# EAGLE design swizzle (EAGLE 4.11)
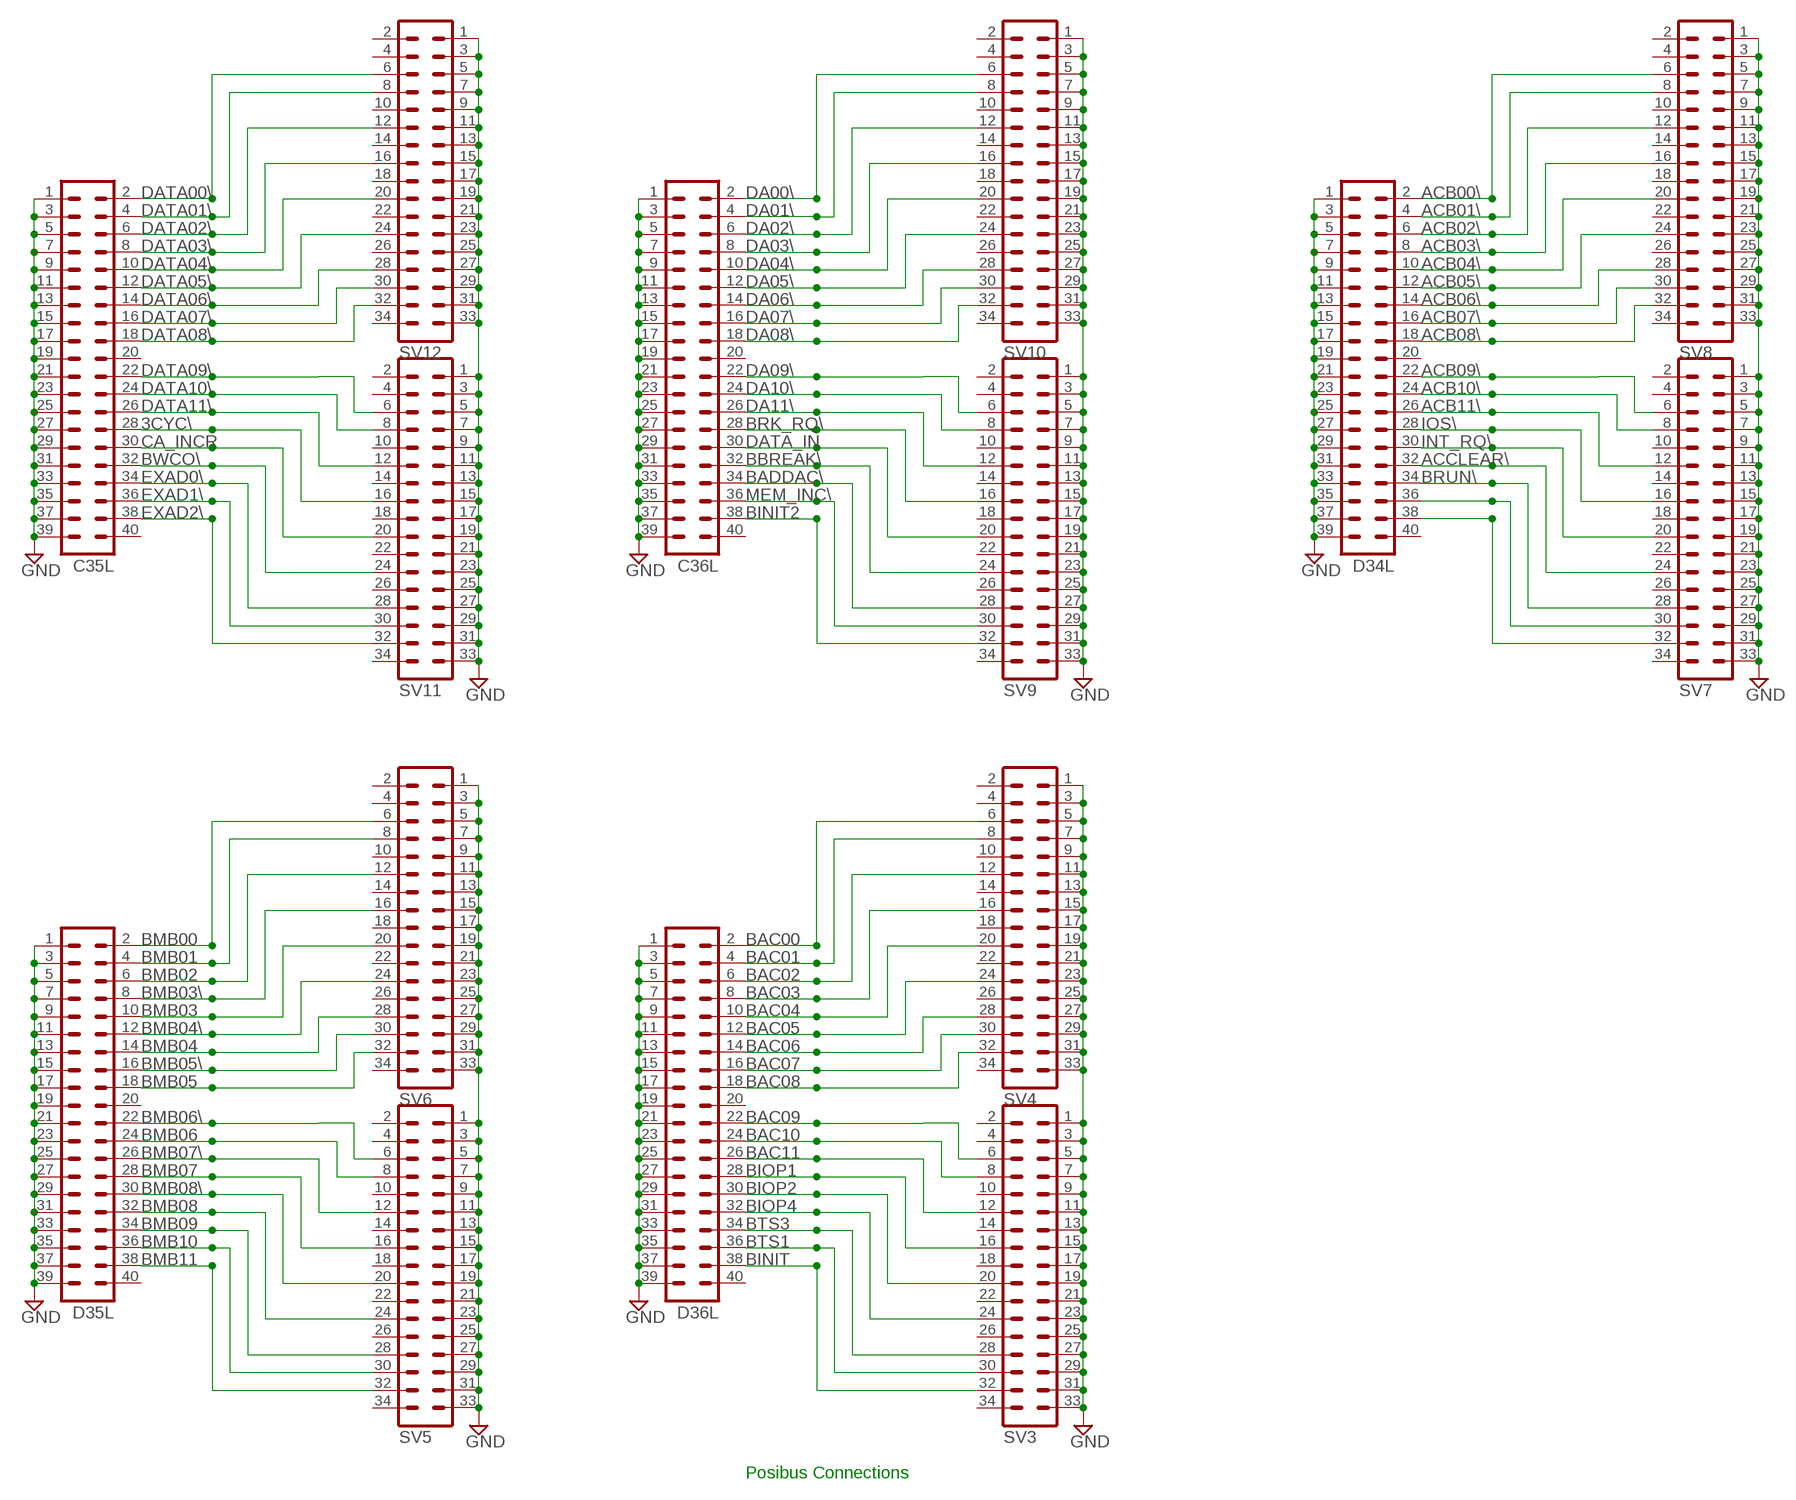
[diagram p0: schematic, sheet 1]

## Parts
C35L  MA20-2  [MA20-2]
C36L  MA20-2  [MA20-2]
D34L  MA20-2  [MA20-2]
D35L  MA20-2  [MA20-2]
D36L  MA20-2  [MA20-2]
SV3  MA17-2  [MA17-2]
SV4  MA17-2  [MA17-2]
SV5  MA17-2  [MA17-2]
SV6  MA17-2  [MA17-2]
SV7  MA17-2  [MA17-2]
SV8  MA17-2  [MA17-2]
SV9  MA17-2  [MA17-2]
SV10  MA17-2  [MA17-2]
SV11  MA17-2  [MA17-2]
SV12  MA17-2  [MA17-2]

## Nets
3CYC\: C35L.28 SV11.16
ACB00\: D34L.2 SV8.6
ACB01\: D34L.4 SV8.8
ACB02\: D34L.6 SV8.12
ACB03\: D34L.8 SV8.16
ACB04\: D34L.10 SV8.20
ACB05\: D34L.12 SV8.24
ACB06\: D34L.14 SV8.28
ACB07\: D34L.16 SV8.30
ACB08\: D34L.18 SV8.32
ACB09\: D34L.22 SV7.6
ACB10\: D34L.24 SV7.8
ACB11\: D34L.26 SV7.12
ACCLEAR\: D34L.32 SV7.24
BAC00: D36L.2 SV4.6
BAC01: D36L.4 SV4.8
BAC02: D36L.6 SV4.12
BAC03: D36L.8 SV4.16
BAC04: D36L.10 SV4.20
BAC05: D36L.12 SV4.24
BAC06: D36L.14 SV4.28
BAC07: D36L.16 SV4.30
BAC08: D36L.18 SV4.32
BAC09: D36L.22 SV3.6
BAC10: D36L.24 SV3.8
BAC11: D36L.26 SV3.12
BADDAC\: C36L.34 SV9.28
BBREAK\: C36L.32 SV9.24
BINIT: D36L.38 SV3.32
BINIT2: C36L.38 SV9.32
BIOP1: D36L.28 SV3.16
BIOP2: D36L.30 SV3.20
BIOP4: D36L.32 SV3.24
BMB00: D35L.2 SV6.6
BMB01: D35L.4 SV6.8
BMB02: D35L.6 SV6.12
BMB03: D35L.10 SV6.20
BMB03\: D35L.8 SV6.16
BMB04: D35L.14 SV6.28
BMB04\: D35L.12 SV6.24
BMB05: D35L.18 SV6.32
BMB05\: D35L.16 SV6.30
BMB06: D35L.24 SV5.8
BMB06\: D35L.22 SV5.6
BMB07: D35L.28 SV5.16
BMB07\: D35L.26 SV5.12
BMB08: D35L.32 SV5.24
BMB08\: D35L.30 SV5.20
BMB09: D35L.34 SV5.28
BMB10: D35L.36 SV5.30
BMB11: D35L.38 SV5.32
BRK_RQ\: C36L.28 SV9.16
BRUN\: D34L.34 SV7.28
BTS1: D36L.36 SV3.30
BTS3: D36L.34 SV3.28
BWCO\: C35L.32 SV11.24
CA_INCR: C35L.30 SV11.20
DA00\: C36L.2 SV10.6
DA01\: C36L.4 SV10.8
DA02\: C36L.6 SV10.12
DA03\: C36L.8 SV10.16
DA04\: C36L.10 SV10.20
DA05\: C36L.12 SV10.24
DA06\: C36L.14 SV10.28
DA07\: C36L.16 SV10.30
DA08\: C36L.18 SV10.32
DA09\: C36L.22 SV9.6
DA10\: C36L.24 SV9.8
DA11\: C36L.26 SV9.12
DATA00\: C35L.2 SV12.6
DATA01\: C35L.4 SV12.8
DATA02\: C35L.6 SV12.12
DATA03\: C35L.8 SV12.16
DATA04\: C35L.10 SV12.20
DATA05\: C35L.12 SV12.24
DATA06\: C35L.14 SV12.28
DATA07\: C35L.16 SV12.30
DATA08\: C35L.18 SV12.32
DATA09\: C35L.22 SV11.6
DATA10\: C35L.24 SV11.8
DATA11\: C35L.26 SV11.12
DATA_IN: C36L.30 SV9.20
EXAD0\: C35L.34 SV11.28
EXAD1\: C35L.36 SV11.30
EXAD2\: C35L.38 SV11.32
GND: C35L.1 C35L.3 C35L.5 C35L.7 C35L.9 C35L.11 C35L.13 C35L.15 C35L.17 C35L.19 C35L.21 C35L.23 C35L.25 C35L.27 C35L.29 C35L.31 C35L.33 C35L.35 C35L.37 C35L.39 C36L.1 C36L.3 C36L.5 C36L.7 C36L.9 C36L.11 C36L.13 C36L.15 C36L.17 C36L.19 C36L.21 C36L.23 C36L.25 C36L.27 C36L.29 C36L.31 C36L.33 C36L.35 C36L.37 C36L.39 D34L.1 D34L.3 D34L.5 D34L.7 D34L.9 D34L.11 D34L.13 D34L.15 D34L.17 D34L.19 D34L.21 D34L.23 D34L.25 D34L.27 D34L.29 D34L.31 D34L.33 D34L.35 D34L.37 D34L.39 D35L.1 D35L.3 D35L.5 D35L.7 D35L.9 D35L.11 D35L.13 D35L.15 D35L.17 D35L.19 D35L.21 D35L.23 D35L.25 D35L.27 D35L.29 D35L.31 D35L.33 D35L.35 D35L.37 D35L.39 D36L.1 D36L.3 D36L.5 D36L.7 D36L.9 D36L.11 D36L.13 D36L.15 D36L.17 D36L.19 D36L.21 D36L.23 D36L.25 D36L.27 D36L.29 D36L.31 D36L.33 D36L.35 D36L.37 D36L.39 SV3.1 SV3.3 SV3.5 SV3.7 SV3.9 SV3.11 SV3.13 SV3.15 SV3.17 SV3.19 SV3.21 SV3.23 SV3.25 SV3.27 SV3.29 SV3.31 SV3.33 SV4.1 SV4.3 SV4.5 SV4.7 SV4.9 SV4.11 SV4.13 SV4.15 SV4.17 SV4.19 SV4.21 SV4.23 SV4.25 SV4.27 SV4.29 SV4.31 SV4.33 SV5.1 SV5.3 SV5.5 SV5.7 SV5.9 SV5.11 SV5.13 SV5.15 SV5.17 SV5.19 SV5.21 SV5.23 SV5.25 SV5.27 SV5.29 SV5.31 SV5.33 SV6.1 SV6.3 SV6.5 SV6.7 SV6.9 SV6.11 SV6.13 SV6.15 SV6.17 SV6.19 SV6.21 SV6.23 SV6.25 SV6.27 SV6.29 SV6.31 SV6.33 SV7.1 SV7.3 SV7.5 SV7.7 SV7.9 SV7.11 SV7.13 SV7.15 SV7.17 SV7.19 SV7.21 SV7.23 SV7.25 SV7.27 SV7.29 SV7.31 SV7.33 SV8.1 SV8.3 SV8.5 SV8.7 SV8.9 SV8.11 SV8.13 SV8.15 SV8.17 SV8.19 SV8.21 SV8.23 SV8.25 SV8.27 SV8.29 SV8.31 SV8.33 SV9.1 SV9.3 SV9.5 SV9.7 SV9.9 SV9.11 SV9.13 SV9.15 SV9.17 SV9.19 SV9.21 SV9.23 SV9.25 SV9.27 SV9.29 SV9.31 SV9.33 SV10.1 SV10.3 SV10.5 SV10.7 SV10.9 SV10.11 SV10.13 SV10.15 SV10.17 SV10.19 SV10.21 SV10.23 SV10.25 SV10.27 SV10.29 SV10.31 SV10.33 SV11.1 SV11.3 SV11.5 SV11.7 SV11.9 SV11.11 SV11.13 SV11.15 SV11.17 SV11.19 SV11.21 SV11.23 SV11.25 SV11.27 SV11.29 SV11.31 SV11.33 SV12.1 SV12.3 SV12.5 SV12.7 SV12.9 SV12.11 SV12.13 SV12.15 SV12.17 SV12.19 SV12.21 SV12.23 SV12.25 SV12.27 SV12.29 SV12.31 SV12.33
INT_RQ\: D34L.30 SV7.20
IOS\: D34L.28 SV7.16
MEM_INC\: C36L.36 SV9.30
N$46: D34L.36 SV7.30
N$47: D34L.38 SV7.32
Unconnected: C35L.20 C35L.40 C36L.20 C36L.40 D34L.20 D34L.40 D35L.20 D35L.40 D36L.20 D36L.40 SV3.2 SV3.4 SV3.10 SV3.14 SV3.18 SV3.22 SV3.26 SV3.34 SV4.2 SV4.4 SV4.10 SV4.14 SV4.18 SV4.22 SV4.26 SV4.34 SV5.2 SV5.4 SV5.10 SV5.14 SV5.18 SV5.22 SV5.26 SV5.34 SV6.2 SV6.4 SV6.10 SV6.14 SV6.18 SV6.22 SV6.26 SV6.34 SV7.2 SV7.4 SV7.10 SV7.14 SV7.18 SV7.22 SV7.26 SV7.34 SV8.2 SV8.4 SV8.10 SV8.14 SV8.18 SV8.22 SV8.26 SV8.34 SV9.2 SV9.4 SV9.10 SV9.14 SV9.18 SV9.22 SV9.26 SV9.34 SV10.2 SV10.4 SV10.10 SV10.14 SV10.18 SV10.22 SV10.26 SV10.34 SV11.2 SV11.4 SV11.10 SV11.14 SV11.18 SV11.22 SV11.26 SV11.34 SV12.2 SV12.4 SV12.10 SV12.14 SV12.18 SV12.22 SV12.26 SV12.34

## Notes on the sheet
- Posibus Connections

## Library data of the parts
C35L C36L D34L D35L D36L = con-lstb:MA20-2: PIN HEADER
SV3-SV12 = con-lstb:MA17-2: PIN HEADER

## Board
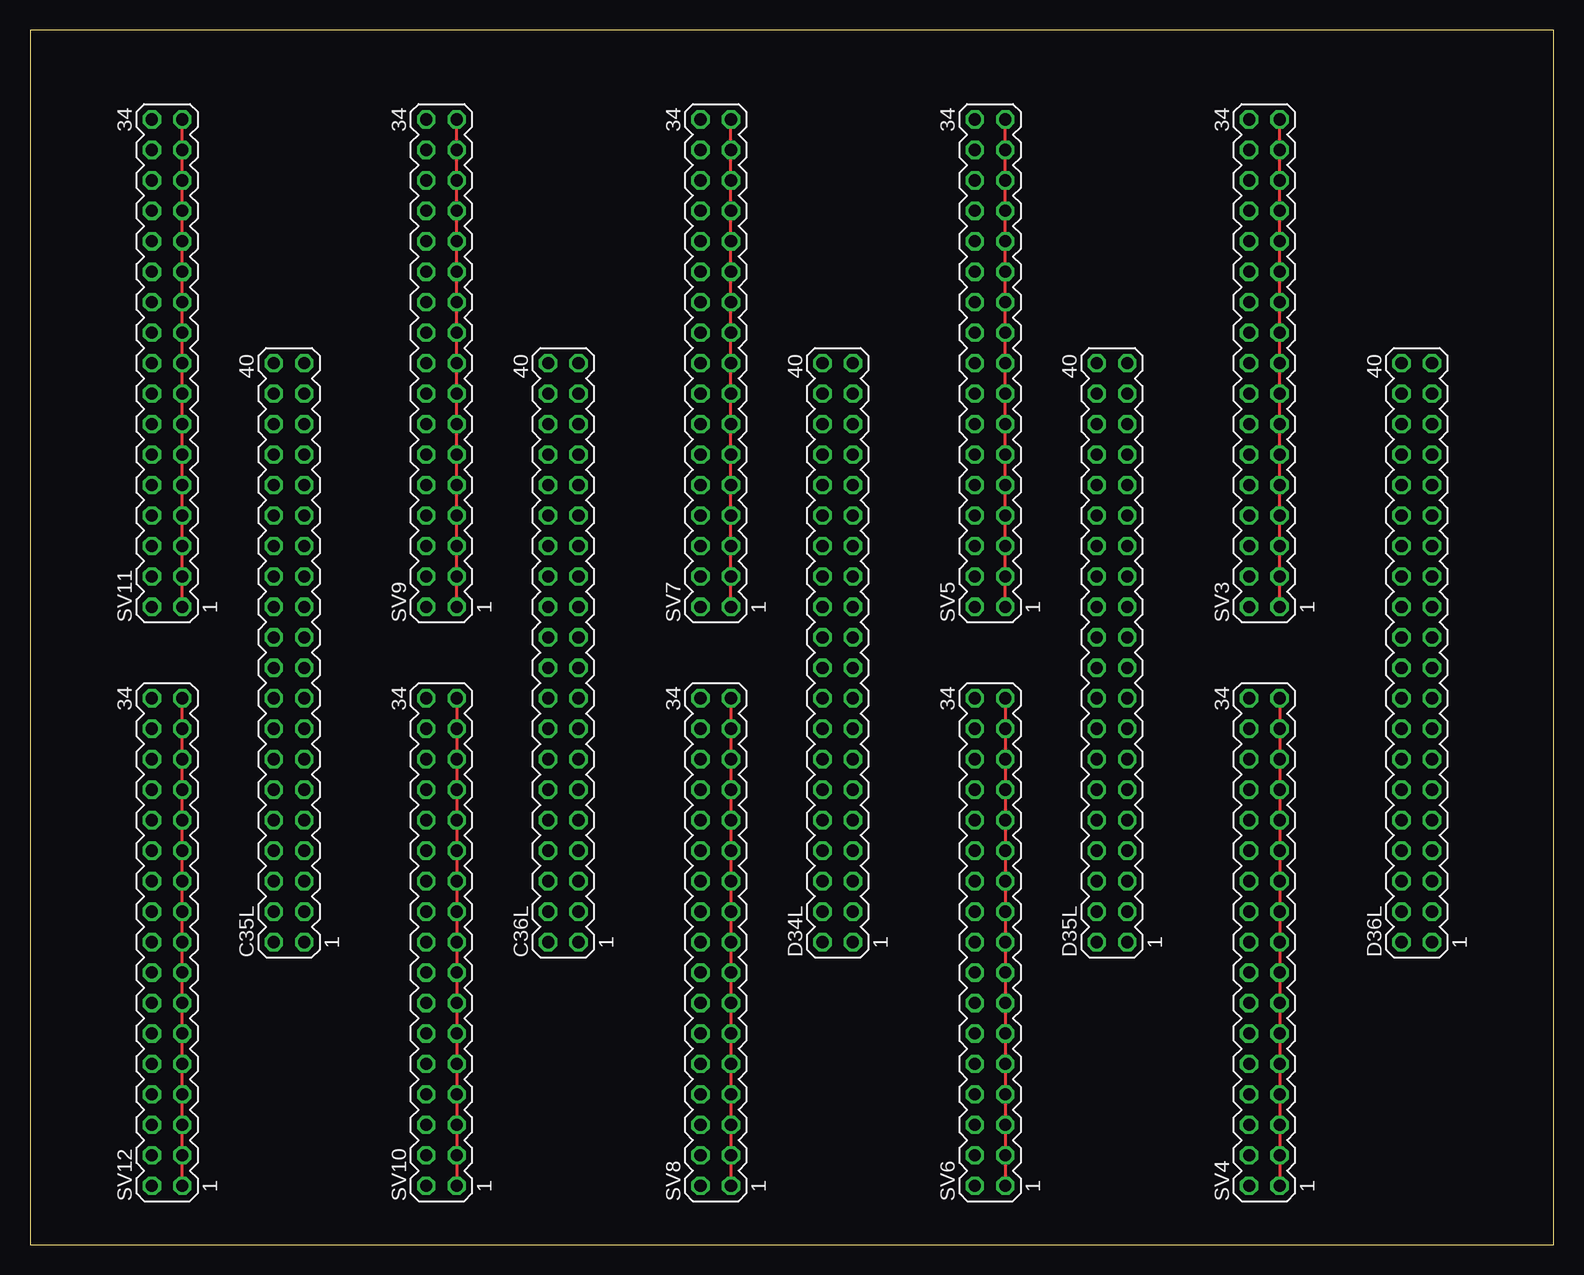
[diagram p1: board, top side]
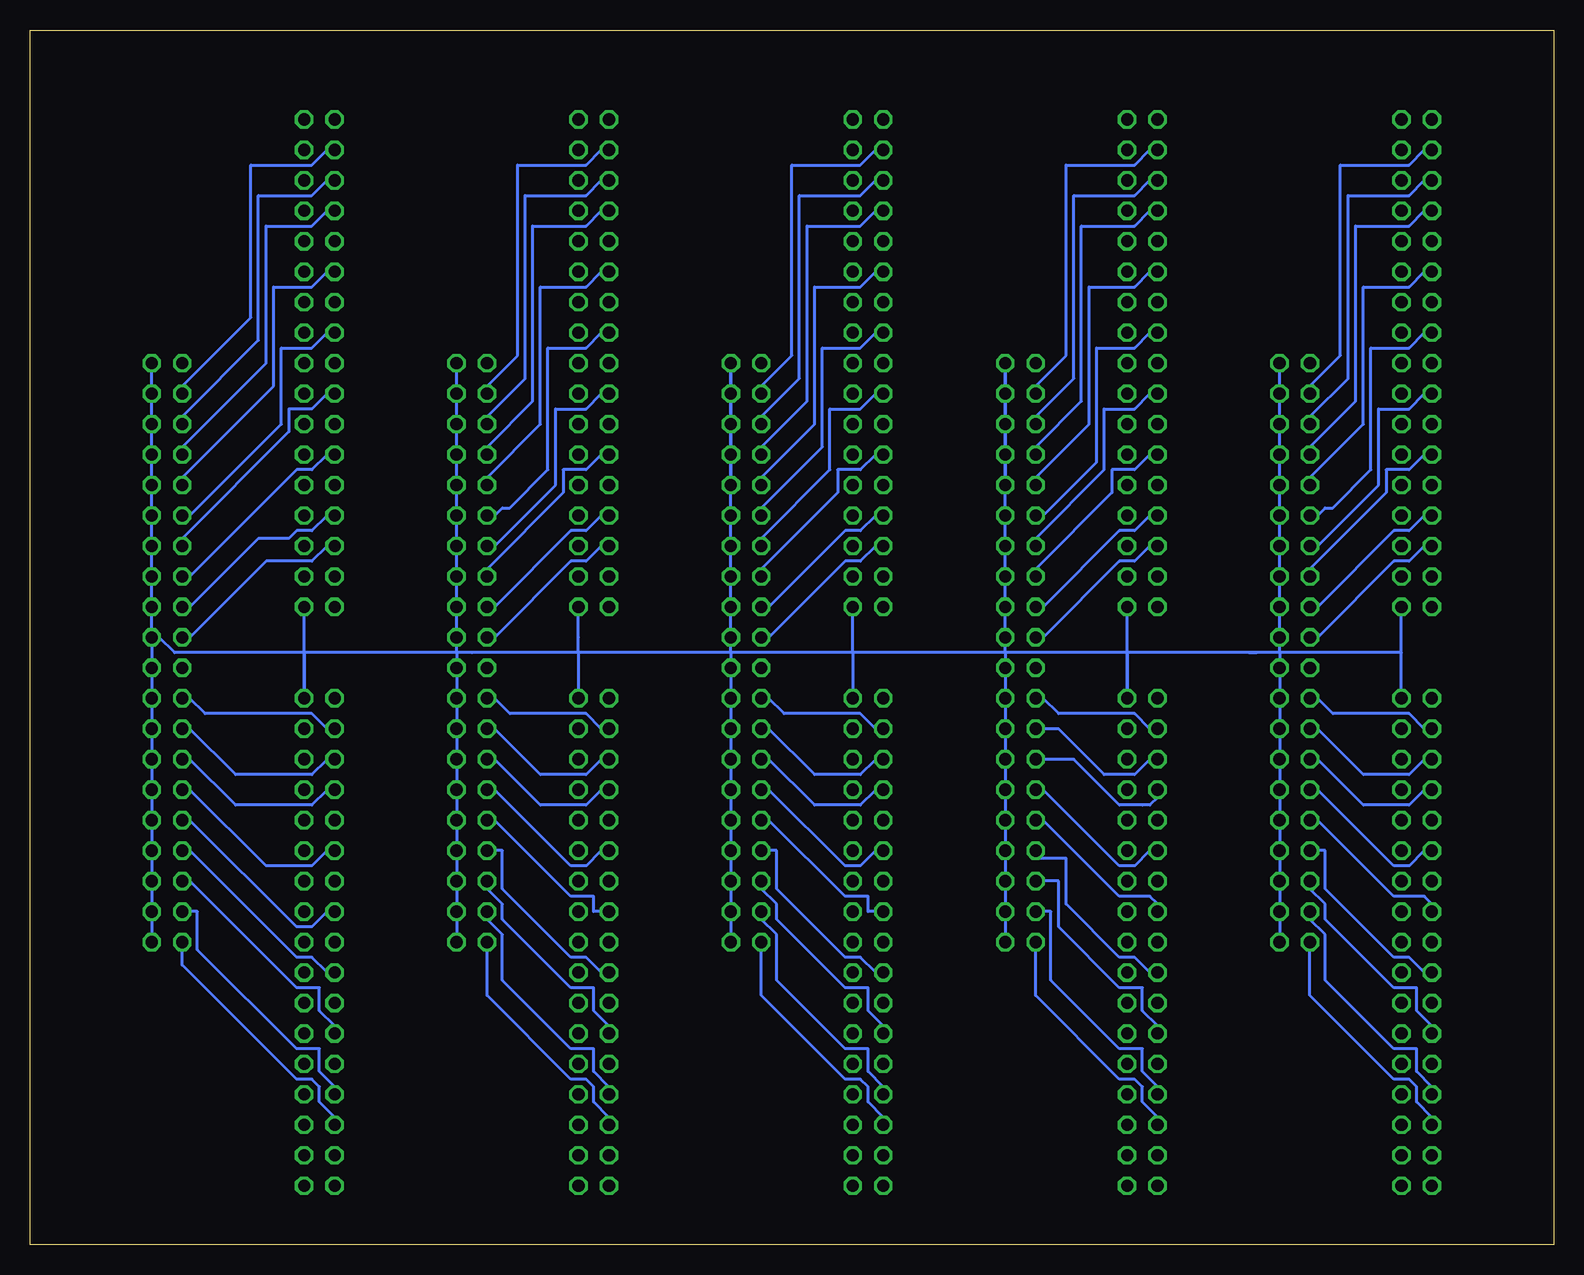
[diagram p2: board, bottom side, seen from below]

Size 126.98 x 101.27 mm. Coordinates in mm from the lower left corner, seen from the top.
Outline: 0,0 126.98,0 126.98,101.27 0,101.27 0,0
Copper layers (1*16): Top 0.035mm / dielectric 1.5mm / Bottom 0.035mm
Design rules "olimex10mil": minimum track width 10mil, minimum drill 24mil, track to track 10mil, track to pad 10mil, pad to pad 10mil, via to via 10mil, smd to smd 10mil, copper to edge 40mil, drill to drill 10mil, minimum pad ring 10mil, minimum via ring 8mil, stop-mask expansion 0mil, vias tented up to drill 0mil, thermal gap 10mil

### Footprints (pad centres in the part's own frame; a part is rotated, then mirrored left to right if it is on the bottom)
MA20-2 = drill 1.016 octagon: 1 -24.13,-1.27; 2 -24.13,1.27; 3 -21.59,-1.27; 4 -21.59,1.27; 5 -19.05,-1.27; 6 -19.05,1.27; 7 -16.51,-1.27; 8 -16.51,1.27; 9 -13.97,-1.27; 10 -13.97,1.27; 11 -11.43,-1.27; 12 -11.43,1.27; 13 -8.89,-1.27; 14 -8.89,1.27; 15 -6.35,-1.27; 16 -6.35,1.27; 17 -3.81,-1.27; 18 -3.81,1.27; 19 -1.27,-1.27; 20 -1.27,1.27; 21 1.27,-1.27; 22 1.27,1.27; 23 3.81,-1.27; 24 3.81,1.27; 25 6.35,-1.27; 26 6.35,1.27; 27 8.89,-1.27; 28 8.89,1.27; 29 11.43,-1.27; 30 11.43,1.27; 31 13.97,-1.27; 32 13.97,1.27; 33 16.51,-1.27; 34 16.51,1.27; 35 19.05,-1.27; 36 19.05,1.27; 37 21.59,-1.27; 38 21.59,1.27; 39 24.13,-1.27; 40 24.13,1.27
MA17-2 = drill 1.016 octagon: 1 -20.32,-1.27; 2 -20.32,1.27; 3 -17.78,-1.27; 4 -17.78,1.27; 5 -15.24,-1.27; 6 -15.24,1.27; 7 -12.7,-1.27; 8 -12.7,1.27; 9 -10.16,-1.27; 10 -10.16,1.27; 11 -7.62,-1.27; 12 -7.62,1.27; 13 -5.08,-1.27; 14 -5.08,1.27; 15 -2.54,-1.27; 16 -2.54,1.27; 17 0,-1.27; 18 0,1.27; 19 2.54,-1.27; 20 2.54,1.27; 21 5.08,-1.27; 22 5.08,1.27; 23 7.62,-1.27; 24 7.62,1.27; 25 10.16,-1.27; 26 10.16,1.27; 27 12.7,-1.27; 28 12.7,1.27; 29 15.24,-1.27; 30 15.24,1.27; 31 17.78,-1.27; 32 17.78,1.27; 33 20.32,-1.27; 34 20.32,1.27

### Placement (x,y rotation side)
C35L  21.59,49.37 90 top
C36L  44.45,49.37 90 top
D34L  67.31,49.37 90 top
D35L  90.17,49.37 90 top
D36L  115.56,49.37 90 top
SV3  102.87,73.49 90 top
SV4  102.87,25.23 90 top
SV5  80.01,73.49 90 top
SV6  80.01,25.23 90 top
SV7  57.14,73.49 90 top
SV8  57.14,25.23 90 top
SV9  34.28,73.49 90 top
SV10  34.28,25.23 90 top
SV11  11.42,73.49 90 top
SV12  11.42,25.23 90 top

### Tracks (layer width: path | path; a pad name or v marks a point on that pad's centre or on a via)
3CYC\
  Bottom 0.254: C35L.28 19.68,58.26 14.6,63.34 14.6,69.68 12.06,69.68 10.79,70.95 SV11.16
ACB00\
  Bottom 0.254: D34L.2 66.04,24.6 66.04,20.79 59.05,13.81 57.78,13.81 57.14,13.17 57.14,11.9 55.88,10.63 SV8.6
ACB01\
  Bottom 0.254: D34L.4 66.04,27.14 64.77,25.87 64.77,22.06 59.05,16.35 57.78,16.35 57.14,16.35 57.14,14.44 55.88,13.17 SV8.8
ACB02\
  Bottom 0.254: SV8.12 55.88,18.25 57.14,19.52 57.14,21.43 59.05,21.43 64.77,27.14 64.77,28.41 66.04,29.68 D34L.6
ACB03\
  Bottom 0.254: SV8.16 56.51,22.7 57.78,23.96 59.05,23.96 64.77,29.68 64.77,32.86 65.4,32.86 D34L.8
ACB04\
  Bottom 0.254: D34L.10 65.4,35.4 59.05,29.05 57.14,29.05 57.14,27.78 56.51,27.78 SV8.20
ACB05\
  Bottom 0.254: D34L.12 65.4,37.94 59.05,31.59 57.78,31.59 56.51,32.86 SV8.24
ACB06\
  Bottom 0.254: D34L.14 65.4,40.48 61.59,36.66 57.78,36.66 56.51,37.94 SV8.28
ACB07\
  Bottom 0.254: D34L.16 65.4,43.02 61.59,39.2 57.78,39.2 56.51,40.48 SV8.30
ACB08\
  Bottom 0.254: SV8.32 56.51,43.02 57.78,44.29 64.13,44.29 65.4,45.55 D34L.18
ACB09\
  Bottom 0.254: SV7.6 56.51,58.26 57.78,56.98 59.05,56.98 65.4,50.63 D34L.22
ACB10\
  Bottom 0.254: SV7.8 56.51,60.8 57.78,59.52 59.05,59.52 65.4,53.18 D34L.24
ACB11\
  Bottom 0.254: D34L.26 66.04,56.35 59.68,62.7 59.68,64.6 57.78,64.6 56.51,65.88 SV7.12
ACCLEAR\
  Bottom 0.254: D34L.32 66.04,63.97 61.59,68.41 61.59,79.84 57.78,79.84 56.51,81.11 SV7.24
BAC00
  Bottom 0.254: D36L.2 114.3,24.6 114.3,23.33 104.77,13.81 103.5,13.81 102.87,13.17 102.87,11.9 101.59,10.63 SV4.6
BAC01
  Bottom 0.254: D36L.4 113.66,27.78 113.03,27.78 113.03,24.6 104.77,16.35 103.5,16.35 102.87,16.35 102.87,14.44 101.59,13.17 SV4.8
BAC02
  Bottom 0.254: SV4.12 101.59,18.25 102.87,19.52 102.87,21.43 104.77,21.43 113.66,30.32 D36L.6
BAC03
  Bottom 0.254: SV4.16 102.23,22.7 103.5,23.96 104.77,23.96 113.66,32.86 D36L.8
BAC04
  Bottom 0.254: D36L.10 113.66,35.4 104.77,26.51 103.5,26.51 102.23,27.78 SV4.20
BAC05
  Bottom 0.254: D36L.12 113.66,37.94 107.31,31.59 103.5,31.59 102.23,32.86 SV4.24
BAC06
  Bottom 0.254: D36L.14 113.66,40.48 109.85,36.66 103.5,36.66 102.23,37.94 SV4.28
BAC07
  Bottom 0.254: D36L.16 113.66,43.02 109.85,39.2 103.5,39.2 102.23,40.48 SV4.30
BAC08
  Bottom 0.254: SV4.32 102.23,43.02 103.5,44.29 112.39,44.29 113.66,45.55 D36L.18
BAC09
  Bottom 0.254: SV3.6 102.23,58.26 103.5,56.98 107.31,56.98 113.66,50.63 D36L.22
BAC10
  Bottom 0.254: SV3.8 102.23,60.8 103.5,59.52 104.77,59.52 105.41,58.89 107.95,58.89 113.66,53.18 D36L.24 114.3,53.81
BAC11
  Bottom 0.254: SV3.12 102.23,65.88 103.5,64.6 104.77,64.6 113.66,55.72 D36L.26
BADDAC\
  Bottom 0.254: C36L.34 43.17,66.51 39.36,70.32 39.36,84.92 34.92,84.92 33.65,86.19 SV9.28
BBREAK\
  Bottom 0.254: C36L.32 43.17,63.97 38.73,68.41 38.73,79.84 34.92,79.84 33.65,81.11 SV9.24
BINIT
  Bottom 0.254: D36L.38 114.3,71.59 108.58,77.3 108.58,90 103.5,90 102.23,91.27 SV3.32
BINIT2
  Bottom 0.254: C36L.38 43.17,71.59 40.63,74.13 40.63,90 34.92,90 33.65,91.27 SV9.32
BIOP1
  Bottom 0.254: D36L.28 114.3,58.89 105.41,67.78 105.41,69.68 103.5,69.68 102.23,70.95 SV3.16
BIOP2
  Bottom 0.254: D36L.30 113.66,60.8 106.04,68.41 106.04,74.77 103.5,74.77 102.23,76.03 SV3.20
BIOP4
  Bottom 0.254: D36L.32 114.3,63.97 106.68,71.59 106.68,79.84 103.5,79.84 102.23,81.11 SV3.24
BMB00
  Bottom 0.254: D35L.2 88.9,24.6 88.9,20.79 81.91,13.81 80.64,13.81 80.01,13.17 80.01,11.9 78.73,10.63 SV6.6
BMB01
  Bottom 0.254: D35L.4 88.9,27.14 87.62,25.87 87.62,22.06 81.91,16.35 80.64,16.35 80.01,16.35 80.01,14.44 78.73,13.17 SV6.8
BMB02
  Bottom 0.254: SV6.12 78.73,18.25 80.01,19.52 80.01,21.43 81.91,21.43 87.62,27.14 87.62,28.41 88.9,29.68 D35L.6
BMB03
  Bottom 0.254: D35L.10 88.26,35.4 81.91,29.05 80.01,29.05 80.01,27.78 79.37,27.78 SV6.20
BMB03\
  Bottom 0.254: SV6.16 79.37,22.7 80.64,23.96 81.91,23.96 87.62,29.68 87.62,32.86 88.26,32.86 D35L.8
BMB04
  Bottom 0.254: D35L.14 88.26,40.48 84.45,36.66 80.64,36.66 79.37,37.94 SV6.28
BMB04\
  Bottom 0.254: D35L.12 88.26,37.94 81.91,31.59 80.64,31.59 79.37,32.86 SV6.24
BMB05
  Bottom 0.254: SV6.32 79.37,43.02 80.64,44.29 86.99,44.29 88.26,45.55 D35L.18
BMB05\
  Bottom 0.254: D35L.16 88.26,43.02 84.45,39.2 80.64,39.2 79.37,40.48 SV6.30
BMB06
  Bottom 0.254: SV5.8 79.37,60.8 80.64,59.52 81.91,59.52 88.26,53.18 D35L.24
BMB06\
  Bottom 0.254: SV5.6 79.37,58.26 80.64,56.98 81.91,56.98 88.26,50.63 D35L.22
BMB07
  Bottom 0.254: D35L.28 88.26,58.26 83.18,63.34 83.18,69.68 80.64,69.68 79.37,70.95 SV5.16
BMB07\
  Bottom 0.254: D35L.26 88.9,56.35 82.55,62.7 82.55,64.6 80.64,64.6 79.37,65.88 SV5.12
BMB08
  Bottom 0.254: D35L.32 88.9,63.97 84.45,68.41 84.45,79.84 80.64,79.84 79.37,81.11 SV5.24
BMB08\
  Bottom 0.254: D35L.30 88.26,60.8 87.62,61.43 86.99,61.43 83.81,64.6 83.81,74.77 80.64,74.77 79.37,76.03 SV5.20
BMB09
  Bottom 0.254: D35L.34 88.9,66.51 85.09,70.32 85.09,84.92 80.64,84.92 79.37,86.19 SV5.28
BMB10
  Bottom 0.254: D35L.36 88.9,69.05 85.72,72.22 85.72,87.46 80.64,87.46 79.37,88.73 SV5.30
BMB11
  Bottom 0.254: D35L.38 88.9,71.59 86.36,74.13 86.36,90 80.64,90 79.37,91.27 SV5.32
BRK_RQ\
  Bottom 0.254: C36L.28 43.17,58.89 37.46,64.6 37.46,69.68 34.92,69.68 33.65,70.95 SV9.16
BRUN\
  Bottom 0.254: D34L.34 66.04,66.51 62.22,70.32 62.22,84.92 57.78,84.92 56.51,86.19 SV7.28
BTS1
  Bottom 0.254: D36L.36 114.3,69.05 107.95,75.4 107.95,87.46 103.5,87.46 102.23,88.73 SV3.30
BTS3
  Bottom 0.254: D36L.34 114.3,66.51 107.31,73.49 107.31,84.92 103.5,84.92 102.23,86.19 SV3.28
BWCO\
  Bottom 0.254: C35L.32 20.32,63.97 15.87,68.41 15.87,79.84 12.06,79.84 10.79,81.11 SV11.24
CA_INCR
  Bottom 0.254: C35L.30 19.68,60.8 19.05,61.43 18.41,61.43 15.23,64.6 15.23,74.77 12.06,74.77 10.79,76.03 SV11.20
DA00\
  Bottom 0.254: C36L.2 43.17,24.6 43.17,20.79 36.19,13.81 34.92,13.81 34.28,13.17 34.28,11.9 33.02,10.63 SV10.6
DA01\
  Bottom 0.254: C36L.4 42.54,27.78 41.9,27.78 41.9,22.06 36.19,16.35 34.92,16.35 34.28,16.35 34.28,14.44 33.02,13.17 SV10.8
DA02\
  Bottom 0.254: SV10.12 33.02,18.25 34.28,19.52 34.28,21.43 36.19,21.43 41.27,26.51 41.27,30.32 42.54,30.32 C36L.6
DA03\
  Bottom 0.254: SV10.16 33.65,22.7 34.92,23.96 36.19,23.96 40.63,28.41 40.63,32.22 43.17,32.22 C36L.8
DA04\
  Bottom 0.254: C36L.10 42.54,35.4 36.19,29.05 34.28,29.05 33.65,29.05 33.02,28.41 SV10.20
DA05\
  Bottom 0.254: C36L.12 42.54,37.94 36.19,31.59 34.92,31.59 33.65,32.86 SV10.24
DA06\
  Bottom 0.254: C36L.14 42.54,40.48 40,40.48 36.19,36.66 34.28,36.66 33.65,36.66 33.02,37.3 SV10.28
DA07\
  Bottom 0.254: C36L.16 42.54,43.02 41.27,43.02 37.46,39.2 34.92,39.2 33.65,40.48 SV10.30
DA08\
  Bottom 0.254: SV10.32 33.65,43.02 34.92,44.29 41.27,44.29 42.54,45.55 C36L.18
DA09\
  Bottom 0.254: SV9.6 33.65,58.26 34.92,56.98 36.19,56.98 42.54,50.63 C36L.22
DA10\
  Bottom 0.254: SV9.8 33.65,60.8 34.92,59.52 36.19,59.52 42.54,53.18 C36L.24
DA11\
  Bottom 0.254: C36L.26 43.17,56.35 36.82,62.7 36.82,64.6 34.92,64.6 33.65,65.88 SV9.12
DATA00\
  Bottom 0.254: C35L.2 20.32,24.6 20.32,20.79 13.33,13.81 12.06,13.81 11.42,13.17 11.42,11.9 10.15,10.63 SV12.6
DATA01\
  Bottom 0.254: C35L.4 20.32,27.14 19.05,25.87 19.05,22.06 13.33,16.35 12.06,16.35 11.42,16.35 11.42,14.44 10.15,13.17 SV12.8
DATA02\
  Bottom 0.254: SV12.12 10.15,18.25 11.42,19.52 11.42,21.43 13.33,21.43 19.05,27.14 19.05,28.41 20.32,29.68 C35L.6
DATA03\
  Bottom 0.254: SV12.16 10.79,22.7 12.06,23.96 13.33,23.96 19.05,29.68 19.05,32.86 19.68,32.86 C35L.8
DATA04\
  Bottom 0.254: C35L.10 19.68,35.4 13.33,29.05 11.42,29.05 10.79,29.05 10.15,28.41 SV12.20
DATA05\
  Bottom 0.254: C35L.12 19.68,37.94 13.33,31.59 12.06,31.59 10.79,32.86 SV12.24
DATA06\
  Bottom 0.254: C35L.14 19.68,40.48 15.87,36.66 12.06,36.66 10.79,37.94 SV12.28
DATA07\
  Bottom 0.254: C35L.16 19.68,43.02 15.87,39.2 12.06,39.2 10.79,40.48 SV12.30
DATA08\
  Bottom 0.254: SV12.32 10.79,43.02 12.06,44.29 18.41,44.29 19.68,45.55 C35L.18
DATA09\
  Bottom 0.254: SV11.6 10.79,58.26 12.06,56.98 13.33,56.98 19.68,50.63 C35L.22
DATA10\
  Bottom 0.254: SV11.8 10.79,60.8 12.06,59.52 13.33,59.52 19.68,53.18 C35L.24
DATA11\
  Bottom 0.254: C35L.26 20.32,56.35 13.96,62.7 13.96,64.6 12.06,64.6 10.79,65.88 SV11.12
DATA_IN
  Bottom 0.254: C36L.30 42.54,60.8 38.09,65.24 38.09,74.77 34.92,74.77 33.65,76.03 SV9.20
EXAD0\
  Bottom 0.254: C35L.34 20.32,66.51 16.51,70.32 16.51,84.92 12.06,84.92 10.79,86.19 SV11.28
EXAD1\
  Bottom 0.254: C35L.36 20.32,69.05 17.14,72.22 17.14,87.46 12.06,87.46 10.79,88.73 SV11.30
EXAD2\
  Bottom 0.254: C35L.38 20.32,71.59 17.78,74.13 17.78,90 12.06,90 10.79,91.27 SV11.32
GND
  Top 0.254: SV12.1 SV12.3 SV12.5 SV12.7 SV12.9 SV12.11 SV12.13 SV12.15 SV12.17 SV12.19 SV12.21 SV12.23 SV12.25 SV12.27 SV12.29 SV12.31 SV12.33 | SV11.1 SV11.3 SV11.5 SV11.7 SV11.9 SV11.11 SV11.13 SV11.15 SV11.17 SV11.19 SV11.21 SV11.23 SV11.25 SV11.27 SV11.29 SV11.31 SV11.33 | SV10.1 SV10.3 SV10.5 SV10.7 SV10.9 SV10.11 SV10.13 SV10.15 SV10.17 SV10.19 SV10.21 SV10.23 SV10.25 SV10.27 SV10.29 SV10.31 SV10.33 35.55,46.19 | SV9.1 SV9.3 SV9.5 SV9.7 SV9.9 SV9.11 SV9.13 SV9.15 SV9.17 SV9.19 SV9.21 SV9.23 SV9.25 SV9.27 SV9.29 SV9.31 SV9.33 | SV4.1 SV4.3 SV4.5 SV4.7 SV4.9 SV4.11 SV4.13 SV4.15 SV4.17 SV4.19 SV4.21 SV4.23 SV4.25 SV4.27 SV4.29 SV4.31 SV4.33 104.14,46.19 | SV3.1 SV3.3 SV3.5 SV3.7 SV3.9 SV3.11 SV3.13 SV3.15 SV3.17 SV3.19 SV3.21 SV3.23 SV3.25 SV3.27 SV3.29 SV3.31 SV3.33 | SV8.1 SV8.3 SV8.5 SV8.7 SV8.9 SV8.11 SV8.13 SV8.15 SV8.17 SV8.19 SV8.21 SV8.23 SV8.25 SV8.27 SV8.29 SV8.31 SV8.33 | SV7.1 SV7.3 SV7.5 SV7.7 SV7.9 SV7.11 SV7.13 SV7.15 SV7.17 SV7.19 SV7.21 SV7.23 SV7.25 SV7.27 SV7.29 SV7.31 SV7.33 | SV6.1 SV6.3 SV6.5 SV6.7 SV6.9 SV6.11 SV6.13 SV6.15 SV6.17 SV6.19 SV6.21 SV6.23 SV6.25 SV6.27 SV6.29 SV6.31 SV6.33 | SV5.1 SV5.3 SV5.5 SV5.7 SV5.9 SV5.11 SV5.13 SV5.15 SV5.17 SV5.19 SV5.21 SV5.23 SV5.25 SV5.27 SV5.29 SV5.31 SV5.33
  Bottom 0.254: C35L.1 C35L.3 C35L.5 C35L.7 C35L.9 C35L.11 C35L.13 C35L.15 C35L.17 C35L.19 22.86,49.37 | C35L.39 C35L.37 C35L.35 22.86,66.51 C35L.33 C35L.31 C35L.29 C35L.27 C35L.25 C35L.23 C35L.21 22.86,49.37 | SV12.33 12.69,49.37 | 12.69,49.37 SV11.1 | C36L.1 C36L.3 C36L.5 C36L.7 C36L.9 C36L.11 C36L.13 C36L.15 C36L.17 | C36L.17 C36L.19 45.71,49.37 | 45.71,49.37 C36L.21 C36L.23 C36L.25 C36L.27 C36L.29 C36L.31 C36L.33 C36L.35 C36L.37 C36L.39 45.71,49.37 | 35.55,46.19 SV9.1 | D36L.1 D36L.3 D36L.5 D36L.7 D36L.9 D36L.11 D36L.13 D36L.15 D36L.17 D36L.19 D36L.21 | D36L.21 D36L.23 D36L.25 D36L.27 D36L.29 D36L.31 D36L.33 D36L.35 D36L.37 D36L.39 | 104.14,46.19 SV3.1 | D34L.1 D34L.3 D34L.5 D34L.7 D34L.9 D34L.11 D34L.13 D34L.15 D34L.17 | D34L.17 D34L.19 68.58,49.37 | 68.58,49.37 D34L.21 D34L.23 D34L.25 D34L.27 D34L.29 D34L.31 D34L.33 D34L.35 D34L.37 D34L.39 68.58,49.37 | D35L.1 D35L.3 D35L.5 D35L.7 D35L.9 D35L.11 D35L.13 D35L.15 D35L.17 D35L.19 91.44,49.37 | 91.44,49.37 D35L.21 D35L.23 D35L.25 D35L.27 D35L.29 D35L.31 D35L.33 D35L.35 D35L.37 D35L.39 | 81.28,49.37 SV6.33 | 81.28,49.37 81.28,50.63 SV5.1 | 104.14,49.37 114.93,49.37 116.2,50.63 D36L.21 | 104.14,49.37 104.14,46.19 | 104.14,46.19 SV4.33 103.5,45.55 | D34L.17 69.21,45.55 | C36L.17 46.35,45.55 | 25.39,49.37 35.55,49.37 | 25.39,49.37 24.76,49.37 | 35.55,49.37 45.71,49.37 | 45.71,49.37 58.41,49.37 | 58.41,49.37 68.58,49.37 | 68.58,49.37 81.28,49.37 | 81.28,49.37 90.17,49.37 | 35.55,49.37 35.55,46.19 | 35.55,46.19 SV10.33 | 58.41,49.37 SV8.33 | 58.41,49.37 SV7.1 | 12.69,49.37 22.86,49.37 | 22.86,49.37 25.39,49.37 | 90.17,49.37 91.44,49.37 | 91.44,49.37 104.14,49.37
  Bottom 0.254: 81.28,49.37 90.17,49.37
INT_RQ\
  Bottom 0.254: D34L.30 66.04,61.43 60.95,66.51 60.95,74.77 57.78,74.77 56.51,76.03 SV7.20
IOS\
  Bottom 0.254: D34L.28 66.04,58.89 60.32,64.6 60.32,69.68 57.78,69.68 56.51,70.95 SV7.16
MEM_INC\
  Bottom 0.254: C36L.36 43.17,69.05 40,72.22 40,87.46 34.92,87.46 33.65,88.73 SV9.30
N$46
  Bottom 0.254: D34L.36 66.04,69.05 62.86,72.22 62.86,87.46 57.78,87.46 56.51,88.73 SV7.30
N$47
  Bottom 0.254: D34L.38 66.04,71.59 63.49,74.13 63.49,90 57.78,90 56.51,91.27 SV7.32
